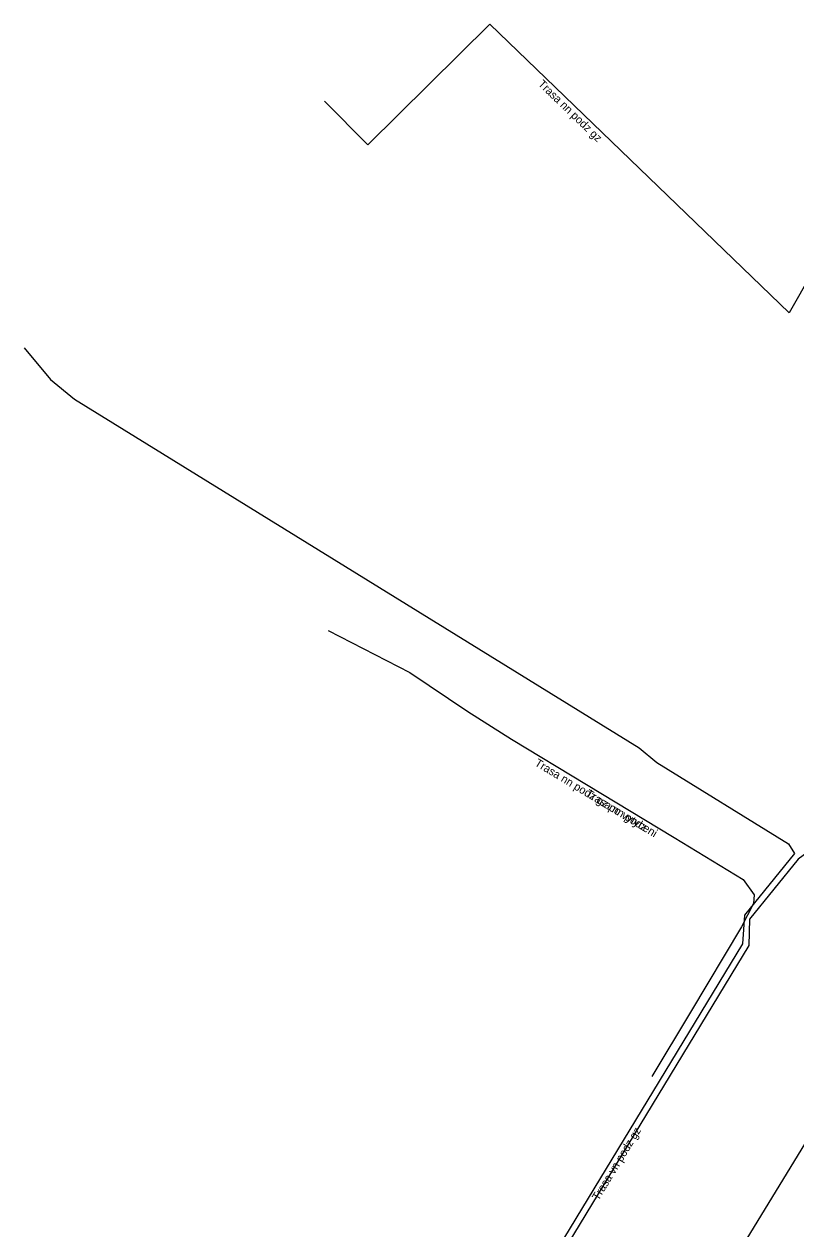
# Model space of a CAD drawing. Extents: x -747115 to -746877, y -964696 to -964505.
# Drawn here: x -747115.2 to -747067.4, y -964617.2 to -964542.6 of the extents above; entities that cross this region are included whole.
import ezdxf

# ---------------------------------------------------------------- set-up
doc = ezdxf.new("R2010")
doc.units = 0
for name, color, linetype in [('Popiskový text - Ostatní atributy Trasy', 7, 'Continuous'), ('Spojnice NN', 7, 'Continuous'), ('Spojnice VN', 7, 'Continuous')]:
    doc.layers.add(name, color=color, linetype=linetype)

msp = doc.modelspace()

# ---------------------------------------------------------------- linework, layer by layer
at = {"layer": 'Spojnice NN'}
for points in [[(-747064.83, -964555.33), (-747067.777, -964560.473), (-747086.318, -964542.581), (-747093.867, -964550.061), (-747096.549, -964547.36)], [(-747096.33, -964580.16), (-747091.27, -964582.75), (-747087.67, -964585.17), (-747084.96, -964586.89), (-747080.33, -964589.69), (-747074.89, -964592.97), (-747070.63, -964595.57), (-747069.93, -964596.52), (-747069.97, -964597.06), (-747070.73, -964598.52), (-747073.88, -964603.79), (-747076.27, -964607.79)], [(-747096.33, -964580.16), (-747091.27, -964582.75), (-747087.67, -964585.17), (-747084.96, -964586.89), (-747080.33, -964589.69), (-747074.89, -964592.97), (-747070.63, -964595.57), (-747069.93, -964596.52), (-747069.97, -964597.06), (-747070.73, -964598.52), (-747073.88, -964603.79), (-747076.27, -964607.79)]]:
    msp.add_lwpolyline(points, dxfattribs=at)
at = {"layer": 'Spojnice VN'}
for points in [[(-747115.161, -964562.638), (-747113.535, -964564.608), (-747112.036, -964565.819), (-747077.062, -964587.416), (-747075.976, -964588.322), (-747067.816, -964593.361), (-747067.439, -964593.977), (-747070.542, -964597.79), (-747070.668, -964599.555), (-747099.412, -964646.937), (-747100.42, -964647.812), (-747104.371, -964654.288), (-747104.045, -964655.22), (-747104.121, -964656.615), (-747104.77, -964658.338), (-747102.022, -964665.691), (-747101.585, -964666.861), (-747101.964, -964667.747), (-747102.963, -964670.7), (-747101.053, -964672.44), (-747099.505, -964673.414), (-747096.735, -964674.966), (-747095.521, -964675.388), (-747093.425, -964675.691)], [(-747096.405, -964674.234), (-747099.095, -964672.726), (-747100.567, -964671.8), (-747102.037, -964670.46), (-747101.216, -964668.033), (-747100.724, -964666.88), (-747100.45, -964665.22), (-747096.645, -964657.647), (-747091.689, -964649.332), (-747088.76, -964647.926), (-747060.905, -964602.312), (-747058.85, -964601.784), (-747056.592, -964598.749), (-747046.609, -964587.253), (-747042.954, -964577.004), (-747043.153, -964575.096), (-747043.06, -964574.7)], [(-747053.608, -964602.449), (-747058.675, -964599.358), (-747059.799, -964598.321), (-747066.592, -964593.873), (-747067.206, -964594.325), (-747070.232, -964598.042), (-747070.274, -964599.675), (-747099.102, -964647.199), (-747100.11, -964648.074), (-747103.931, -964654.334), (-747103.641, -964655.162), (-747103.725, -964656.699), (-747104.342, -964658.338), (-747101.634, -964665.587), (-747101.155, -964666.871), (-747101.59, -964667.89), (-747102.5, -964670.58), (-747100.81, -964672.12), (-747099.3, -964673.07), (-747096.57, -964674.6)]]:
    msp.add_lwpolyline(points, dxfattribs=at)

# ---------------------------------------------------------------- texts
at = {"layer": 'Popiskový text - Ostatní atributy Trasy'}
for s, rotation, p in [('Trasa nn podz gz', 316.02053, (-747083.361, -964546.337)), ('Trasa nn podz gz po vytyceni', 328.91249, (-747083.576, -964588.491)), ('Trasa nn podz', 328.91249, (-747080.421, -964590.394)), ('Trasa vn podz gz', 58.75716, (-747079.585, -964615.506))]:
    msp.add_text(s, height=0.5, rotation=rotation, dxfattribs=at).set_placement(p)

doc.saveas('drawing.dxf')
